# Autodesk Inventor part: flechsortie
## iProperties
Shininess: 64.0
Length Units: 11269
Angle Units: 11279
Time Units: 11290
Mass Units: 11283
Length Display Precision: 3
Angle Display Precision: 2
Compacted: True
Part Number: flechsortie
Document SubType Name: Modeling
Created: 2003-10
Material: Par défaut
Designer: Maison
Density: 0.0
Volumn: 0.0
Area: 0.0
PropertySet Name: Model Information
Control State: 0
Master: False
Checked Out: False
Author: Maison
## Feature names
1. Extrusion1
